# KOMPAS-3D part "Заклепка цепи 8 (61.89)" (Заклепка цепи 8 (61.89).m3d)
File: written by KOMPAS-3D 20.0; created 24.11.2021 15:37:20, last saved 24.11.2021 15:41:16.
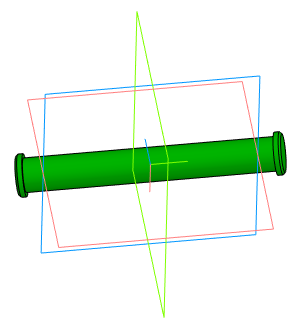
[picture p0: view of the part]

Document properties: Полное имя файла: C:\!WORK!\ЗИГ-18.240.00\Цепь\Заклепка цепи 8 (61.89).m3d

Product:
- Part/product: Заклепка цепи 8 (61.89)
    Материал: Сталь 45  ГОСТ 1050-2013 (density 7810 kg/m3)
    Масса: 0.0249879

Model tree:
1. Эскиз:1
2. Элемент вращения:1
     Угол 1 = 360
3. Фаска:1  (with: Элемент вращения:1)  (labels: Сталь 45  ГОСТ 1050-2013)
     Угол = 45; Длина 1 = 0.5; Длина 2 = 0.5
